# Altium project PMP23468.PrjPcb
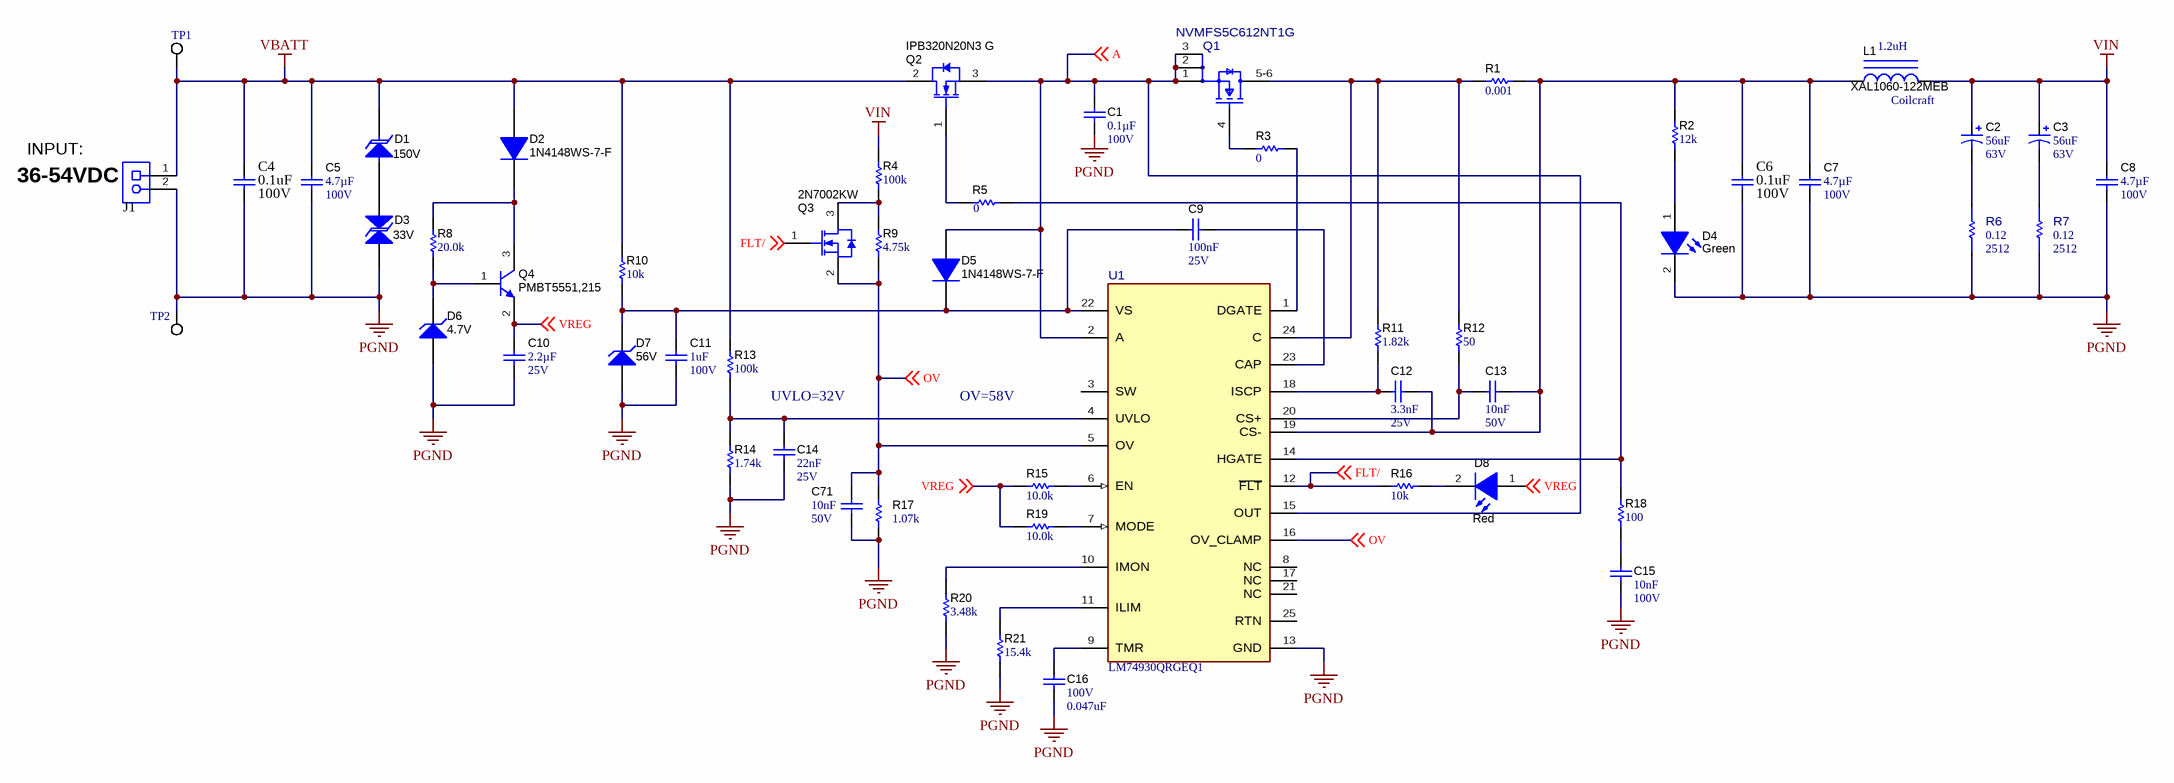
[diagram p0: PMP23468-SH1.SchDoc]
CopyrightYear: 2018; PCB_Layout: Who did the Layout?; PCB_Rev: E1; PRJ_Customer: Public Release; PRJ_Engineer: Enter name of project lead; PRJ_Number: XXX###; PRJ_Title: Change in menu Project|Project Options|Parameters; SCH_Rev: E1; TechSupport: http://www.ti.com/support; TID: N/A
2 sheets, 157 parts. Net scope: global (net labels, ports and power ports of the same name join across sheets).
Board file: PMP23468A.PcbDoc
Sheets:
  PMP23468-SH1.SchDoc
  PMP23468-SH2.SchDoc

## Sheet PMP23468-SH1.SchDoc: LM25143-Q1 Two Phases
size 431 x 279 mm; Date: Not shown in title block; ApprovedBy: Not shown in title block; CheckedBy: Not shown in title block; Author: Not shown in title block; CompanyName: Not shown in title block; Engineer: Not shown in title block; Organization: Not shown in title block; Address1: Not shown in title block; Address2: Not shown in title block; Address3: Not shown in title block; Address4: Not shown in title block; DocumentNumber: 1; Revision: Use project parameter SCH_Rev; SheetNumber: 1; SheetTotal: 2; PageSetup: Record=PageOptions¦CenterHorizontal=True¦CenterVertical=True¦PrintScale=0.96¦XCorrection=1.00¦YCorrection=1.00¦PrintKind=0¦BorderSize=5000000¦LeftOffset=0¦BottomOffset=0¦Orientation=2¦PaperLength=1000¦PaperWidth=1000¦Scale=100¦PaperSource=7¦PrintQuality=600¦MediaType=1¦DitherType=10¦PaperKind=11" x 17"¦PrintScaleMode=1

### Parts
C1  ValueDisplayed: 0.1µF  VDC_V: 100V  [0603]  (hidden comment: GCJ188L8EL104KA07D)
C2  VDC_V: 63V  ValueDisplayed: 56uF  [SM_RADIAL_10BMM]  (hidden comment: EEHZC1J560P)
C3  VDC_V: 63V  ValueDisplayed: 56uF  [SM_RADIAL_10BMM]  (hidden comment: EEHZC1J560P)
C4  Value2: 100V  ValueDisplayed: 0.1uF  [0805_HV]  (hidden comment: C0805C104K1RACTU)
C5  VDC_V: 100V  ValueDisplayed: 4.7µF  [1210_220]  (hidden comment: GCM32DC72A475KE02L)
C6  Value2: 100V  ValueDisplayed: 0.1uF  [0805_HV]  (hidden comment: C0805C104K1RACTU)
C7  VDC_V: 100V  ValueDisplayed: 4.7µF  [1210_220]  (hidden comment: GCM32DC72A475KE02L)
C8  VDC_V: 100V  ValueDisplayed: 4.7µF  [1210_220]  (hidden comment: GCM32DC72A475KE02L)
C9  Cap_F: 100nF  VDC_V: 25V  [0603]  (hidden comment: CGA3E2X7R1E104K080AA)
C10  Cap_F: 2.2µF  VDC_V: 25V  [0805_HV]  (hidden comment: GCM21BR71E225KA73L)
C11  VDC_V: 100V  ValueDisplayed: 1uF  [1206_180]  (hidden comment: GCM31CR72A105KA03)
C12  Cap_F: 3.3nF  VDC_V: 25V  [0603]  (hidden comment: GRM188R71E332KA01D)
C13  Cap_F: 10nF  VDC_V: 50V  [0603]  (hidden comment: GCM188R71H103KA37D)
C14  Cap_F: 22nF  VDC_V: 25V  [0603]  (hidden comment: C0603C223K3RACTU)
C15  Cap_F: 10nF  VDC_V: 100V  [0603]  (hidden comment: CGA3E2X7R2A103K080AA)
C16  VDC_V: 100V  ValueDisplayed: 0.047uF  [0603]  (hidden comment: CGA3E3X7S2A473K080AB)
C71  Cap_F: 10nF  VDC_V: 50V  [0603]  (hidden comment: GCM188R71H103KA37D)
D1  value 150V  [SMB]  (hidden comment: SMBJ150A-13-F)
D2  1N4148WS-7-F  [SOD-323]
D3  value 33V  [SMB-Bi]  (hidden comment: SMBJ33CA-13-F)
D4  value Green  [LED_LTST-C190]  (hidden comment: LTST-C190GKT)
D5  1N4148WS-7-F  [SOD-323]
D6  value 4.7V  [SOD-323]  (hidden comment: MM3Z4V7ST1G)
D7  value 56V  [SOD-123]  (hidden comment: MMSZ5263BT1G)
D8  value Red  [LED_LTST-C170_Red]  (hidden comment: LTST-C170KRKT)
J1  1714971  [Phoenix_1714971]  (value not drawn)
L1  XAL1060-122MEB  Manufacturer: Coilcraft  ValueDisplayed: 1.2uH  [XAL1060]
Q1  NVMFS5C612NT1G  [FP-NVMFS5C612NT1G_DFN5-MFG]
Q2  IPB320N20N3 G  [DDPAK]
Q3  2N7002KW  [SOT-323]
Q4  PMBT5551,215  [SOT-23]
R1  ValueDisplayed: 0.001  [2010]  (hidden comment: WSL20101L000FEA)
R2  ValueDisplayed: 12k  [0603]  (hidden comment: CRCW060312K0JNEA)
R3  ValueDisplayed: 0  [0603]  (hidden comment: ERJ-3GEY0R00V)
R4  ValueDisplayed: 100k  [0603]  (hidden comment: CRCW0603100KFKEA)
R5  ValueDisplayed: 0  [0603]  (hidden comment: ERJ-3GEY0R00V)
R6  PackageReference: 2512  Res_ohm: 0.12  [FP-TLRH3AWTTER120F_2512-MFG]  (hidden comment: TLRH3AWTTER120F)
R7  PackageReference: 2512  Res_ohm: 0.12  [FP-TLRH3AWTTER120F_2512-MFG]  (hidden comment: TLRH3AWTTER120F)
R8  ValueDisplayed: 20.0k  [0805_HV]  (hidden comment: ERJ-6ENF2002V)
R9  ValueDisplayed: 4.75k  [0603]  (hidden comment: CRCW06034K75FKEA)
R10  ValueDisplayed: 10k  [1206]  (hidden comment: CRCW120610K0JNEA)
R11  ValueDisplayed: 1.82k  [0603]  (hidden comment: CRCW0603464RFKEA)
R12  ValueDisplayed: 50  [0603]  (hidden comment: CRCW060350R0FKEA)
R13  ValueDisplayed: 100k  [0603]  (hidden comment: CRCW0603100KFKEA)
R14  ValueDisplayed: 1.74k  [0603]  (hidden comment: CRCW06031K74FKEA)
R15  ValueDisplayed: 10.0k  [0603]  (hidden comment: RMCF0603FT10K0)
R16  ValueDisplayed: 10k  [1206]  (hidden comment: CRCW120610K0JNEA)
R17  ValueDisplayed: 1.07k  [0603]  (hidden comment: CRCW06031K10FKEA)
R18  ValueDisplayed: 100  [0603]  (hidden comment: CRCW0603100RJNEA)
R19  ValueDisplayed: 10.0k  [0603]  (hidden comment: RMCF0603FT10K0)
R20  ValueDisplayed: 3.48k  [0603]  (hidden comment: RC0603FR-0736KL)
R21  ValueDisplayed: 15.4k  [0603]  (hidden comment: CRCW060324K3FKEA)
TP1  5015  [Testpoint_Keystone_Miniature]  (value not drawn)
TP2  5015  [Testpoint_Keystone_Miniature]  (value not drawn)
U1  LM74930QRGEQ1  [RGE0024T-MFG]

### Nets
PGND: C1.2 C4.1 C5.2 C6.2 C7.2 C8.2 C10.2 C11.2 C14.2 C15.2 C16.2 C71.1 D3.2 D4.2(K) D6.2(A) D7.2(A) J1.2 R6.1 R7.1 R14.2 R17.2 R20.1 R21.2 TP2.1 U1.13(GND)
VBATT: C4.2 C5.1 D1.1(K) D2.2(A) J1.1 Q2.2(D) R10.1 R13.1 TP1.1
VIN: C2.1(+) C3.1(+) C8.1 L1.2 R4.1
A: C1.1 D5.2(A) Q1.1(S) Q1.2(S) Q1.3(S) Q2.3(S) U1.2(A) U1.15(OUT) ; off-sheet A
FLT/: Q3.1(G) R16.1 U1.12(~{FLT}) ; off-sheet FLT/
OV: C71.2 Q3.2(S) R9.2 R17.1 U1.5(OV) U1.16(OV_CLAMP) ; off-sheet OV
VREG: C10.1 D8.1(A) Q4.2(E) R15.1 R19.1 ; off-sheet VREG
NetC2_2: C2.2(-) R6.2
NetC3_2: C3.2(-) R7.2
NetC6_1: C6.1 C7.1 C12.2 C13.2 L1.1 R1.2 R2.1 U1.19(CS-)
NetC9_1: C9.1 C11.1 D5.1(K) D7.1(K) R10.2 U1.22(VS)
NetC9_2: C9.2 U1.23(CAP)
NetC12_1: C12.1 R11.2 U1.18(ISCP)
NetC13_1: C13.1 R12.2 U1.20(CS+)
NetC14_1: C14.1 R13.2 R14.1 U1.4(UVLO)
NetC15_1: C15.1 R18.2
NetC16_1: C16.1 U1.9(TMR)
NetD1_2: D1.2(A) D3.1
NetD2_1: D2.1(K) Q4.3(C) R8.1
NetD4_1: D4.1(A) R2.2
NetD6_1: D6.1(K) Q4.1(B) R8.2
NetD8_2: D8.2(K) R16.2
NetQ1_4: Q1.4(G) R3.1
NetQ1_5-6: Q1.5-6(D) R1.1 R11.1 R12.1 U1.24(C)
NetQ2_1: Q2.1(G) R5.1
NetQ3_3: Q3.3(D) R4.2 R9.1
NetR3_2: R3.2 U1.1(DGATE)
NetR5_2: R5.2 R18.1 U1.14(HGATE)
NetR15_2: R15.2 U1.6(EN)
NetR19_2: R19.2 U1.7(MODE)
NetR20_2: R20.2 U1.10(IMON)
NetR21_1: R21.1 U1.11(ILIM)

Not connected (* = marked no-connect by the designer): U1 3(SW) 8(NC) 17(NC) 21(NC) 25(RTN)

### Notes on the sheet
- INPUT:
- (near J1) 36-54VDC
- UVLO=32V
- OV=58V

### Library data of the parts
C1 = CMP-0860999-1: CAP, CERM, 0.1 µF, 100 V,+/- 10%, X8L, AEC-Q200 Grade 0, 0603; Manufacturer: MuRata; Cap_F: 100nF; TaMax_C: 150°C; SizeAreaWB_mm2: 4.68; SizeArea_mm2: 1.28; Value: 0.1uF; SizeZ_mm: 1; AEC Qualified: Y; SizeX_mm: 1.6; AEC Grade: 0; SizeY_mm: 0.8; U/M: EA; TaMin_C: -55°C; Polarized: N; AEC Category: Q200
C2 C3 = CMP-0012603-3: CAP, Polymer Hybrid, 56 uF, 63 V, +/- 20%, 30 ohm, 10x10 SMD; Manufacturer: Panasonic; TaMin_C: -55°C; ESR_ohm: 30; Polarized: Y; SizeAreaWB_mm2: 159.9; Value1: 30 ohm; Value: 56uF; TaMax_C: 125°C; SizeZ_mm: 10.2; SizeX_mm: 11; SizeY_mm: 10.3; SizeArea_mm2: 113.3; CompType: Capacitor; Cap_F: 56µF; IRMS_A: 1.4A; AEC Category: Q200
C4 C6 = CMP-0007722-2: CAP, CERM, 0.1 uF, 100 V, +/- 10%, X7R, 0805; Manufacturer: Kemet; TaMin_C: -55°C; ESR_ohm: 0.064; Polarized: N; SizeAreaWB_mm2: 6.75; Value1: 0.064 ohm; U/M: EA; Value: 0.1uF; TaMax_C: 125°C; SizeZ_mm: 1.45; SizeX_mm: 2; SizeY_mm: 1.25; Cap_Case: 0805; SizeArea_mm2: 2.5; CompType: Capacitor; Cap_F: 100nF; IRMS_A: 1.64A; AEC Category: Q200
C5 C7 C8 = CMP-0082268-1: CAP, CERM, 4.7 µF, 100 V,+/- 10%, X7S, AEC-Q200 Grade 1, 1210; Manufacturer: MuRata; TaMin_C: -55°C; ESR_ohm: 1m; Polarized: N; SizeAreaWB_mm2: 14.7; Value1: 0.001 ohm; U/M: EA; Value: 4.7uF; TaMax_C: 125°C; SizeZ_mm: 2.2; SizeX_mm: 3.2; SizeY_mm: 2.5; Cap_Case: 1210; SizeArea_mm2: 8; AEC Qualified: Y; IRMS_A: 6A; AEC Grade: 1; AEC Category: Q200
C9 = CMP-0007077-5: CAP, CERM, 0.1 uF, 25 V, +/- 10%, X7R, AEC-Q200 Grade 1, 0603; Manufacturer: TDK; TaMin_C: -55°C; Polarized: N; SizeAreaWB_mm2: 4.68; Value1: Unknown; U/M: EA; Value: 0.1uF; TaMax_C: 125°C; SizeZ_mm: 1; SizeX_mm: 1.6; SizeY_mm: 0.8; SizeArea_mm2: 1.28; AEC Qualified: Y; AEC Category: Q200
C10 = CMP-0083622-1: CAP, CERM, 2.2 µF, 25 V,+/- 10%, X7R, AEC-Q200 Grade 1, 0805; Manufacturer: MuRata; TaMin_C: -55°C; Polarized: N; SizeAreaWB_mm2: 6.75; U/M: EA; Value: 2.2uF; TaMax_C: 125°C; SizeZ_mm: 1.45; SizeX_mm: 2; SizeY_mm: 1.25; Cap_Case: 0805; SizeArea_mm2: 2.5; AEC Qualified: Y; AEC Grade: 1; AEC Category: Q200
C11 = CMP-0008815-2: CAP, CERM, 1 uF, 100 V, +/- 10%, X7R, AEC-Q200 Grade 1, 1206; Manufacturer: MuRata; TaMin_C: -55°C; Polarized: N; SizeAreaWB_mm2: 10.92; Value1: Unknown; U/M: EA; Value: 1uF; TaMax_C: 125°C; SizeZ_mm: 1.8; SizeX_mm: 3.2; SizeY_mm: 1.6; Cap_Case: 1206; SizeArea_mm2: 5.12; AEC Qualified: Y; Cap_F: 1µF; AEC Grade: 1; AEC Category: Q200
C12 = CMP-0007418-4: CAP, CERM, 3300 pF, 25 V, +/- 10%, X7R, 0603; Manufacturer: MuRata; TaMin_C: -55°C; Polarized: N; SizeAreaWB_mm2: 4.68; Value1: Unknown; U/M: EA; Value: 3300pF; TaMax_C: 125°C; SizeZ_mm: 1; SizeX_mm: 1.6; SizeY_mm: 0.8; SizeArea_mm2: 1.28; AEC Category: Q200
C13 = CMP-0007143-4: CAP, CERM, 0.01 uF, 50 V, +/- 10%, X7R, AEC-Q200 Grade 1, 0603; Manufacturer: MuRata; TaMin_C: -55°C; Polarized: N; SizeAreaWB_mm2: 4.68; Value1: Unknown; U/M: EA; Value: 0.01uF; TaMax_C: 125°C; SizeZ_mm: 1; SizeX_mm: 1.6; SizeY_mm: 0.8; SizeArea_mm2: 1.28; AEC Qualified: Y; AEC Category: Q200
C14 = CMP-0006899-4: CAP, CERM, 0.022 uF, 25 V, +/- 10%, X7R, 0603; Manufacturer: Kemet; TaMin_C: -55°C; Polarized: N; SizeAreaWB_mm2: 4.68; Value1: Unknown; U/M: EA; TaMax_C: 125°C; SizeZ_mm: 1; SizeX_mm: 1.6; SizeY_mm: 0.8; SizeArea_mm2: 1.28; AEC Category: Q200
C15 = CMP-0007082-4: CAP, CERM, 0.01 uF, 100 V, +/- 10%, X7R, AEC-Q200 Grade 1, 0603; Manufacturer: TDK; TaMin_C: -55°C; ESR_ohm: 0.2354; Polarized: N; SizeAreaWB_mm2: 4.68; Value1: 0.235428 ohm; U/M: EA; Value: 0.01uF; TaMax_C: 125°C; SizeZ_mm: 1; SizeX_mm: 1.6; SizeY_mm: 0.8; SizeArea_mm2: 1.28; AEC Qualified: Y; IRMS_A: 396.995mA; AEC Category: Q200
C16 = CMP-0007101-4: CAP, CERM, 0.047 uF, 100 V, +/- 10%, X7S, AEC-Q200 Grade 1, 0603; Manufacturer: TDK; TaMin_C: -55°C; ESR_ohm: 89.796m; Polarized: N; SizeAreaWB_mm2: 4.68; Value1: 0.089796 ohm; U/M: EA; TaMax_C: 125°C; SizeZ_mm: 1; SizeX_mm: 1.6; SizeY_mm: 0.8; SizeArea_mm2: 1.28; AEC Qualified: Y; Cap_F: 47nF; IRMS_A: 567.484mA; AEC Category: Q200
C71 = CMP-0007143-4: CAP, CERM, 0.01 uF, 50 V, +/- 10%, X7R, AEC-Q200 Grade 1, 0603 (stack on top of R17 resistor); Manufacturer: MuRata; TaMin_C: -55°C; Polarized: N; SizeAreaWB_mm2: 4.68; Value1: Unknown; U/M: EA; Value: 0.01uF; TaMax_C: 125°C; SizeZ_mm: 1; SizeX_mm: 1.6; SizeY_mm: 0.8; SizeArea_mm2: 1.28; AEC Qualified: Y; AEC Category: Q200
D1 = CMP-0005577-3: Diode, TVS, Uni, 150 V, 243 Vc, SMB; Manufacturer: Diodes Inc.; Vbr_Max: 192.5V; Ipp: 2.5A; AEC Category: Q101; SizeArea_mm2: 21.336; Value1: 600W; SizeAreaWB_mm2: 44.156; Vc: 243V; SizeZ_mm: 2.6; SizeX_mm: 5.6; SizeY_mm: 3.81; Vbr_Min: 167V
D2 D5 = CMP-0079597-2: Diode, Switching, 75 V, 0.15 A, AEC-Q101, SOD-323; Manufacturer: Diodes Inc.; SizeX_mm: 2.7; Vf_V: 1.25V; AEC Qualified: Y; SizeArea_mm2: 3.645; AEC Category: Q101; SizeAreaWB_mm2: 8.695; Io_A: 150mA; SizeZ_mm: 1; Value1: 0.15A; SizeY_mm: 1.35; TJmax_C: 150°C; Vr_V: 75V; Value: 75V
D3 = CMP-0005564-3: Diode, TVS, Bi, 33 V, SMB; Manufacturer: Diodes Inc.; SizeX_mm: 5.6; Ppk: 600W; SizeAreaWB_mm2: 44.156; SizeZ_mm: 2.6; SizeArea_mm2: 21.336; SizeY_mm: 3.81; AEC Category: Q101
D4 = CMP-0002827-3: LED, Green, SMD; Manufacturer: Lite-On; Power_TotalModule: 100mW; Value2: 2.1V; Io_A: 20mA; Value1: 0.1W
D6 = CMP-0085737-1: Diode, Zener, 4.7 V, 300 mW, SOD-323; Manufacturer: ON Semiconductor; SizeArea_mm2: 3.645; SizeZ_mm: 1; SizeAreaWB_mm2: 8.695; RJA_CperW: 416; SizeY_mm: 1.35; Power_W: 300mW; AEC Qualified: N; SizeX_mm: 2.7; AEC Category: Q101; Value1: 0.3W
D7 = CMP-0005738-4: Diode, Zener, 56 V, 500 mW, AEC-Q101, SOD-123; Manufacturer: ON Semiconductor; AEC Qualified: Y; Value1: 0.5W; SizeY_mm: 1.7; SizeX_mm: 3.85; SizeArea_mm2: 6.545; AEC Category: Q101; SizeAreaWB_mm2: 13.095; Power_W: 500mW; SizeZ_mm: 1.35; RJA_CperW: 340
D8 = CMP-0002829-3: LED, Red, SMD; Manufacturer: Lite-On; SizeZ_mm: 1.2; Value1: W; SizeY_mm: 1.25; Value2: 2V; SizeArea_mm2: 2.5; SizeX_mm: 2; SizeAreaWB_mm2: 6.75; Io_A: 20mA; Type: AlInGaP
J1 = CMP-0055554-1: Receptacle, 9.52mm, 2x1, TH; Manufacturer: Phoenix Contact; CNHeader: FALSE; Current_A: 32A; Gender: Female; Cert_CSA: Y; Voltage_V: 1kV; Row_Count: 1; Pitch_mm: 9.52
L1 = CMP-0060959-1: Inductor, Shielded, Composite, 1.2 uH, 26.3 A, 0.0025 ohm, AEC-Q200 Grade 1, SMD; Isat: 43A @ 30% inductance drop; Irms: 26.3A @ 40C rise; Green_Lifecycle: Not Set; SizeAreaWB_mm2: 159.6; DCR_ohm: 2.5m; Green_REACh: Incomplete; Value: 1.2uH; Imax_A: 26.3A; SizeZ_mm: 6; SizeX_mm: 11.3; SizeY_mm: 10; SizeArea_mm2: 113; Ind_H: 1.2µH; AEC Qualified: Y; AEC Grade: 1; AEC Category: Q200
Q1 = CMP-0093804-1: Single N-Channel Power MOSFET 60V, 225A, 1.65ohm; Manufacturer: onsemi; Turn On Delay Time: 13.2ns; Standoff Height: 0mm; TJmax_C: +175°C; Rdson45_ohm: 1.35m; Turn Off Delay Time: 46.5ns; Number Of N Channels: 1; Vgs_V: 20V; Reverse Recovery Charge: 160nC; AEC Grade: Grade 0; Threshold Vgs Min: 2V; Rthja Max: 39°C/W; QgTyp_nC: 62nC @ 10V; Reverse Recovery Time: 90ns; VdsMax_V: 1.2V; Input Capacitace At Vds: 4900pF @ 25V; Power_W: 3.8W; AEC Qualified: Yes; SizeZ_mm: 1.1mm; Pulse Drain Current: 900A; ChMode: False; Threshold Vgs Max: 4V; Typ Forward Diode Voltage: 0.81V
Q2 = CMP-0001084-3: MOSFET, N-CH, 200 V, 34 A, DDPAK; Manufacturer: Infineon Technologies; Alternate Manufacturer: None; Value2: 22 nC; QgTyp_nC: 22; SizeZ_mm: 4.445; Value: 200V; SizeAreaWB_mm2: 209.6992; Rdson45_ohm: 0.25; Value1: 0.2; SizeArea_mm2: 154.8892; AEC Category: Q101; ChMode: Enhancement; SizeY_mm: 10.16; SizeX_mm: 15.245; ChType: N; Vgs_V: 20V; IdsMax_A: 34A
Q3 = CMP-0000774-1: MOSFET, N-CH, 60 V, 0.31 A, SOT-323; Manufacturer: Fairchild Semiconductor; Alternate Manufacturer: None; SizeZ_mm: 1.1; Value: 60V; SizeAreaWB_mm2: 10.24; Rdson45_ohm: 1.6; Value1: 1; SizeArea_mm2: 4.84; AEC Category: Q101; SizeY_mm: 2.2; ChType: N; Vgs_V: 2.1V; IdsMax_A: 310mA; U/M: EA
Q4 = CMP-0750056-1: Transistor, NPN, 160 V, 0.3 A, SOT-23; Manufacturer: Nexperia; TaMax_C: 150°C; IcRated_A: 300mA; SizeX_mm: 2.5; NPN: 1; AEC Qualified: N; TaMin_C: -65°C; PNP: 0; SizeArea_mm2: 7.5; SizeY_mm: 3; SizeAreaWB_mm2: 14; CompType: BJT; SizeZ_mm: 1.1; Vcesat1_V: 150mV; Value: 160 V; Value2: 250; Vceo_V: 160V; AEC Category: Q101; Value1: 0.3 A
R1 = CMP-0016548-2: RES, 0.001, 1%, 0.5 W, 2010; Manufacturer: Vishay-Dale; Power_W: 500mW; TempCo: 275 ppm/C; Value_Code: 1L000; U/M: EA; Value: 0.001; EIA_Code: E96; Res_ohm: 1m; SizeX_mm: 5; SizeY_mm: 2.5; SizeZ_mm: 1.66; Value2: 0.5W; SizeArea_mm2: 12.5; AEC Category: Q200
R2 = CMP-0025711-4: RES, 12 k, 5%, 0.1 W, AEC-Q200 Grade 0, 0603; Manufacturer: Vishay-Dale; Power_W: 100mW; TempCo: 200 ppm/C; Value_Code: 12k0; Value: 12k; EIA_Code: E24; SizeX_mm: 1.6; SizeY_mm: 0.8; SizeZ_mm: 1; Value2: 0.1W; SizeArea_mm2: 1.28; AEC Qualified: Y; VDC_V: 75V; AEC Category: Q200; AEC Grade: 0
R3 R5 = CMP-0025874-4: RES, 0, 5%, 0.1 W, AEC-Q200 Grade 0, 0603; Manufacturer: Panasonic; Power_W: 100mW; TempCo: 600 ppm/C; Value_Code: 0000; Value: 0; EIA_Code: E24; SizeX_mm: 1.6; SizeY_mm: 0.8; SizeZ_mm: 1; Value2: 0.1W; SizeArea_mm2: 1.28; AEC Qualified: Y; VDC_V: 50V; AEC Category: Q200; SizeAreaWB_mm2: 4.68
R4 R13 = CMP-0021990-4: RES, 100 k, 1%, 0.1 W, AEC-Q200 Grade 0, 0603; Manufacturer: Vishay-Dale; Power_W: 100mW; TempCo: 100 ppm/C; Value: 100k; EIA_Code: E96; SizeX_mm: 1.6; SizeY_mm: 0.8; SizeZ_mm: 1; Value2: 0.1W; SizeArea_mm2: 1.28; AEC Qualified: Y; VDC_V: 75V; AEC Category: Q200; AEC Grade: 0
R6 R7 = CMP-0088454-1: 120 mOhms ±1% 2W Chip Resistor 2512 (6432 Metric) Automotive AEC-Q200, Current Sense Metal Element; Manufacturer: KOA Speer; TempCo: 50ppm/°C; SizeZ_mm: 0.7mm; AEC Qualified: Yes; AEC Grade: Grade 0
R8 = CMP-0021614-3: RES, 20.0 k, 1%, 0.125 W, AEC-Q200 Grade 0, 0805; Manufacturer: Panasonic; Power_W: 125mW; TempCo: 100 ppm/C; Value_Code: 20k0; Value: 20.0k; EIA_Code: E96; Res_ohm: 20k; SizeX_mm: 2; SizeY_mm: 1.25; SizeZ_mm: 1.45; Value2: 0.125W; SizeArea_mm2: 2.5; AEC Qualified: Y; AEC Category: Q200; AEC Grade: 0; SizeAreaWB_mm2: 6.75
R9 = CMP-0022456-4: RES, 4.75 k, 1%, 0.1 W, AEC-Q200 Grade 0, 0603; Manufacturer: Vishay-Dale; Power_W: 100mW; TempCo: 100 ppm/C; Value_Code: 4k75; Value: 4.75k; EIA_Code: E96; SizeX_mm: 1.6; SizeY_mm: 0.8; SizeZ_mm: 1; Value2: 0.1W; SizeArea_mm2: 1.28; AEC Qualified: Y; VDC_V: 75V; AEC Category: Q200; AEC Grade: 0
R10 R16 = CMP-0018576-3: RES, 10 k, 5%, 0.25 W, AEC-Q200 Grade 0, 1206; Manufacturer: Vishay-Dale; Power_W: 250mW; TempCo: 200 ppm/C; Value_Code: 10k0; Value: 10k; EIA_Code: E24; SizeX_mm: 3.2; SizeY_mm: 1.6; SizeZ_mm: 1.35; Value2: 0.25W; SizeArea_mm2: 5.12; AEC Qualified: Y; VDC_V: 200V; AEC Category: Q200; AEC Grade: 0
R11 = CMP-0022134-4: RES, 1.82 k, 1%, 0.1 W, AEC-Q200 Grade 0, 0603; Manufacturer: Vishay-Dale; PartNumber: CRCW06031K82FKEA; Power_W: 100mW; TempCo: 100 ppm/C; Value_Code: 1k82; Value: 1.82k; EIA_Code: E96; SizeX_mm: 1.6; SizeY_mm: 0.8; SizeZ_mm: 1; Value2: 0.1W; SizeArea_mm2: 1.28; AEC Qualified: Y; VDC_V: 75V; AEC Category: Q200; AEC Grade: 0
R12 = CMP-0022479-4: RES, 50, 1%, 0.1 W, AEC-Q200 Grade 0, 0603; Manufacturer: Vishay-Dale; Power_W: 100mW; TempCo: 100 ppm/C; Value_Code: 50R0; Value: 50; SizeX_mm: 1.6; SizeY_mm: 0.8; SizeZ_mm: 1; Value2: 0.1W; SizeArea_mm2: 1.28; AEC Qualified: Y; VDC_V: 75V; AEC Category: Q200; AEC Grade: 0
R14 = CMP-0022132-4: RES, 1.74 k, 1%, 0.1 W, AEC-Q200 Grade 0, 0603; Manufacturer: Vishay-Dale; Power_W: 100mW; TempCo: 100 ppm/C; Value_Code: 1k74; Value: 1.74k; EIA_Code: E96; SizeX_mm: 1.6; SizeY_mm: 0.8; SizeZ_mm: 1; Value2: 0.1W; SizeArea_mm2: 1.28; AEC Qualified: Y; VDC_V: 75V; AEC Category: Q200; AEC Grade: 0
R15 R19 = CMP-0023341-3: RES, 10.0 k, 1%, 0.1 W, AEC-Q200 Grade 0, 0603; Manufacturer: Stackpole Electronics Inc; Power_W: 100mW; TempCo: 100 ppm/C; Value_Code: 10k0; U/M: EA; Value: 10.0k; EIA_Code: E96; Res_ohm: 10k; SizeX_mm: 1.6; SizeY_mm: 0.8; SizeZ_mm: 1; Value2: 0.1W; SizeArea_mm2: 1.28; AEC Qualified: Y; VDC_V: 75V; AEC Grade: 0; AEC Category: Q200
R17 = CMP-0022112-4: RES, 1.07 k, 1%, 0.1 W, AEC-Q200 Grade 0, 0603; Manufacturer: Vishay-Dale; PartNumber: CRCW06031K07FKEA; Power_W: 100mW; TempCo: 100 ppm/C; Value_Code: 1k07; Value: 1.07k; EIA_Code: E96; SizeX_mm: 1.6; SizeY_mm: 0.8; SizeZ_mm: 1; Value2: 0.1W; SizeArea_mm2: 1.28; AEC Qualified: Y; VDC_V: 75V; AEC Category: Q200; AEC Grade: 0
R18 = CMP-0025700-4: RES, 100, 5%, 0.1 W, AEC-Q200 Grade 0, 0603; Manufacturer: Vishay-Dale; Power_W: 100mW; TempCo: 200 ppm/C; Value_Code: 100R; Value: 100; EIA_Code: E24; SizeX_mm: 1.6; SizeY_mm: 0.8; SizeZ_mm: 1; Value2: 0.1W; SizeArea_mm2: 1.28; AEC Qualified: Y; VDC_V: 75V; AEC Category: Q200; AEC Grade: 0
R20 = CMP-0022377-4: RES, 3.48 k, 1%, 0.1 W, AEC-Q200 Grade 0, 0603; Manufacturer: Vishay-Dale; PartNumber: CRCW06033K48FKEA; Power_W: 100mW; TempCo: 100 ppm/C; Value_Code: 3k48; Value: 3.48k; EIA_Code: E96; SizeX_mm: 1.6; SizeY_mm: 0.8; SizeZ_mm: 1; Value2: 0.1W; SizeArea_mm2: 1.28; AEC Qualified: Y; VDC_V: 75V; AEC Category: Q200; AEC Grade: 0
R21 = CMP-0022067-4: RES, 15.4 k, 1%, 0.1 W, AEC-Q200 Grade 0, 0603; Manufacturer: Vishay-Dale; PartNumber: CRCW060315K4FKEA; Power_W: 100mW; TempCo: 100 ppm/C; Value_Code: 15k4; Value: 15.4k; EIA_Code: E96; SizeX_mm: 1.6; SizeY_mm: 0.8; SizeZ_mm: 1; Value2: 0.1W; SizeArea_mm2: 1.28; AEC Qualified: Y; VDC_V: 75V; AEC Category: Q200; AEC Grade: 0
TP1 TP2 = CMP-0055152-2: Test Point, Miniature, SMT; Manufacturer: Keystone Electronics; CNHeader: FALSE; Green_Lifecycle: Active; Green_REACh: Passed; CT: TRUE
U1 = CMP-0021701-1: Ideal Diode Surge Stopper with Circuit breaker, overvoltage protection and fault output; Manufacturer: Texas Instruments; SizeZ_mm: 1mm; AEC Qualified: Yes; AEC Grade: Grade 1; Max Supply Voltage: 65V; Min Supply Voltage: 3V; Nominal Supply Current: 650-700uA; Number Of Outputs: 1; Standoff Height: 0mm; TaMax_C: +125°C; TaMin_C: -40°C; TJmax_C: +150°C

## Sheet PMP23468-SH2.SchDoc: LM25143-Q1 Two Phases
size 431 x 279 mm; Date: Not shown in title block; ApprovedBy: Not shown in title block; CheckedBy: Not shown in title block; Author: Not shown in title block; CompanyName: Not shown in title block; Engineer: Not shown in title block; Organization: Not shown in title block; Address1: Not shown in title block; Address2: Not shown in title block; Address3: Not shown in title block; Address4: Not shown in title block; DocumentNumber: 2; Revision: Use project parameter SCH_Rev; SheetNumber: 2; SheetTotal: 2; PageSetup: Record=PageOptions¦CenterHorizontal=True¦CenterVertical=True¦PrintScale=0.96¦XCorrection=1.00¦YCorrection=1.00¦PrintKind=0¦BorderSize=5000000¦LeftOffset=0¦BottomOffset=0¦Orientation=2¦PaperLength=1000¦PaperWidth=1000¦Scale=100¦PaperSource=7¦PrintQuality=600¦MediaType=1¦DitherType=10¦PaperKind=11" x 17"¦PrintScaleMode=1
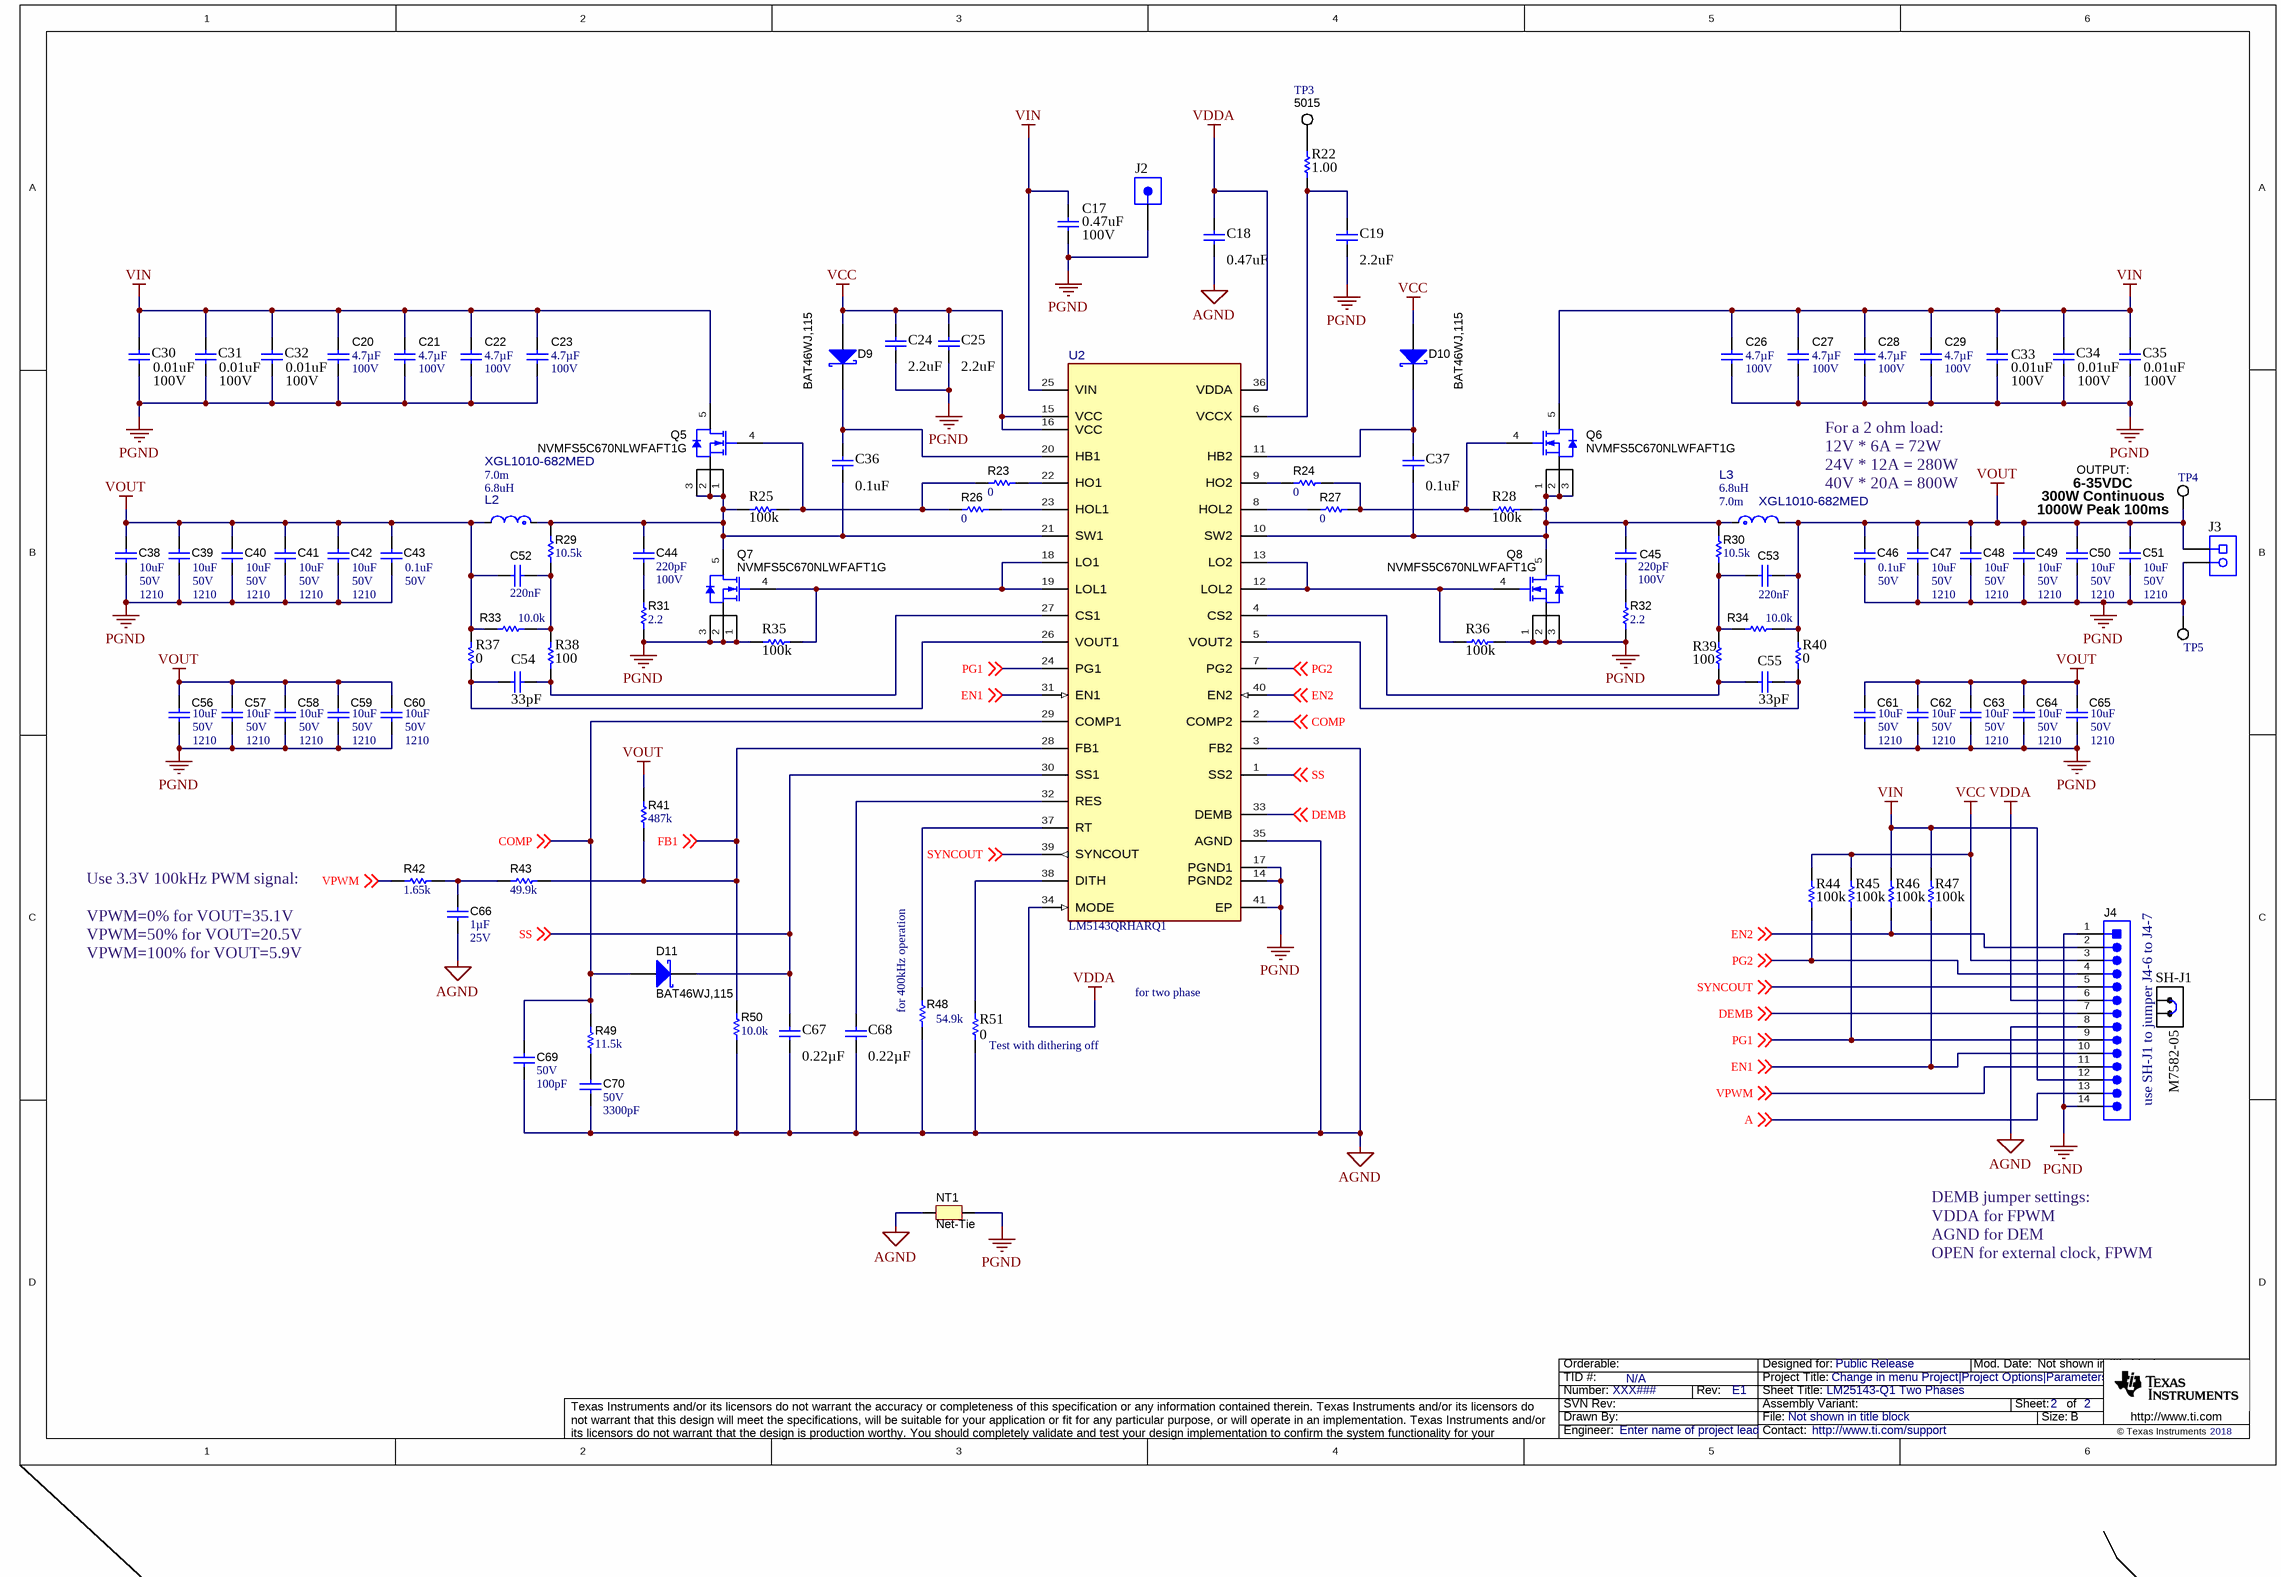
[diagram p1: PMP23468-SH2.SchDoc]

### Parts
C17  VDC_V: 100V  ValueDisplayed: 0.47uF  [0805L]  (hidden comment: GRM21BR72A474KA73L)
C18  ValueDisplayed: 0.47uF  [0603L]  (hidden comment: GCM188R71C474KA55D)
C19  ValueDisplayed: 2.2uF  [0603L]  (hidden comment: GRM188R71A225KE15D)
C20  VDC_V: 100V  ValueDisplayed: 4.7µF  [1210_220]  (hidden comment: GCM32DC72A475KE02L)
C21  VDC_V: 100V  ValueDisplayed: 4.7µF  [1210_220]  (hidden comment: GCM32DC72A475KE02L)
C22  VDC_V: 100V  ValueDisplayed: 4.7µF  [1210_220]  (hidden comment: GCM32DC72A475KE02L)
C23  VDC_V: 100V  ValueDisplayed: 4.7µF  [1210_220]  (hidden comment: GCM32DC72A475KE02L)
C24  ValueDisplayed: 2.2uF  [0603L]  (hidden comment: GRM188R71A225KE15D)
C25  ValueDisplayed: 2.2uF  [0603L]  (hidden comment: GRM188R71A225KE15D)
C26  VDC_V: 100V  ValueDisplayed: 4.7µF  [1210_220]  (hidden comment: GCM32DC72A475KE02L)
C27  VDC_V: 100V  ValueDisplayed: 4.7µF  [1210_220]  (hidden comment: GCM32DC72A475KE02L)
C28  VDC_V: 100V  ValueDisplayed: 4.7µF  [1210_220]  (hidden comment: GCM32DC72A475KE02L)
C29  VDC_V: 100V  ValueDisplayed: 4.7µF  [1210_220]  (hidden comment: GCM32DC72A475KE02L)
C30  VDC_V: 100V  ValueDisplayed: 0.01uF  [0402S]  (hidden comment: CGA2B3X7S2A103K050BB)
C31  VDC_V: 100V  ValueDisplayed: 0.01uF  [0402S]  (hidden comment: CGA2B3X7S2A103K050BB)
C32  VDC_V: 100V  ValueDisplayed: 0.01uF  [0402S]  (hidden comment: CGA2B3X7S2A103K050BB)
C33  VDC_V: 100V  ValueDisplayed: 0.01uF  [0402S]  (hidden comment: CGA2B3X7S2A103K050BB)
C34  VDC_V: 100V  ValueDisplayed: 0.01uF  [0402S]  (hidden comment: CGA2B3X7S2A103K050BB)
C35  VDC_V: 100V  ValueDisplayed: 0.01uF  [0402S]  (hidden comment: CGA2B3X7S2A103K050BB)
C36  ValueDisplayed: 0.1uF  [0603L]  (hidden comment: CGA3E2X7R1E104K080AA)
C37  ValueDisplayed: 0.1uF  [0603L]  (hidden comment: CGA3E2X7R1E104K080AA)
C38  PackageReference: 1210  VDC_V: 50V  ValueDisplayed: 10uF  [1210_270]  (hidden comment: UMJ325KB7106KMHT)
C39  PackageReference: 1210  VDC_V: 50V  ValueDisplayed: 10uF  [1210_270]  (hidden comment: UMJ325KB7106KMHT)
C40  PackageReference: 1210  VDC_V: 50V  ValueDisplayed: 10uF  [1210_270]  (hidden comment: UMJ325KB7106KMHT)
C41  PackageReference: 1210  VDC_V: 50V  ValueDisplayed: 10uF  [1210_270]  (hidden comment: UMJ325KB7106KMHT)
C42  PackageReference: 1210  VDC_V: 50V  ValueDisplayed: 10uF  [1210_270]  (hidden comment: UMJ325KB7106KMHT)
C43  Value2: 50V  ValueDisplayed: 0.1uF  [0603]  (hidden comment: CGA3E2X7R1H104K080AA)
C44  Cap_F: 220pF  VDC_V: 100V  [0603_HV]  (hidden comment: 06031C221KAT2A)
C45  Cap_F: 220pF  VDC_V: 100V  [0603_HV]  (hidden comment: 06031C221KAT2A)
C46  Value2: 50V  ValueDisplayed: 0.1uF  [0603]  (hidden comment: CGA3E2X7R1H104K080AA)
C47  PackageReference: 1210  VDC_V: 50V  ValueDisplayed: 10uF  [1210_270]  (hidden comment: UMJ325KB7106KMHT)
C48  PackageReference: 1210  VDC_V: 50V  ValueDisplayed: 10uF  [1210_270]  (hidden comment: UMJ325KB7106KMHT)
C49  PackageReference: 1210  VDC_V: 50V  ValueDisplayed: 10uF  [1210_270]  (hidden comment: UMJ325KB7106KMHT)
C50  PackageReference: 1210  VDC_V: 50V  ValueDisplayed: 10uF  [1210_270]  (hidden comment: UMJ325KB7106KMHT)
C51  PackageReference: 1210  VDC_V: 50V  ValueDisplayed: 10uF  [1210_270]  (hidden comment: UMJ325KB7106KMHT)
C52  Cap_F: 220nF  [0603]  (hidden comment: CGA3E3X7R1H224K080AB)
C53  Cap_F: 220nF  [0603]  (hidden comment: CGA3E3X7R1H224K080AB)
C54  ValueDisplayed: 33pF  [0603L]  (hidden comment: 06031A330JAT2A)
C55  ValueDisplayed: 33pF  [0603L]  (hidden comment: 06031A330JAT2A)
C56  PackageReference: 1210  VDC_V: 50V  ValueDisplayed: 10uF  [1210_270]  (hidden comment: UMJ325KB7106KMHT)
C57  PackageReference: 1210  VDC_V: 50V  ValueDisplayed: 10uF  [1210_270]  (hidden comment: UMJ325KB7106KMHT)
C58  PackageReference: 1210  VDC_V: 50V  ValueDisplayed: 10uF  [1210_270]  (hidden comment: UMJ325KB7106KMHT)
C59  PackageReference: 1210  VDC_V: 50V  ValueDisplayed: 10uF  [1210_270]  (hidden comment: UMJ325KB7106KMHT)
C60  PackageReference: 1210  VDC_V: 50V  ValueDisplayed: 10uF  [1210_270]  (hidden comment: UMJ325KB7106KMHT)
C61  PackageReference: 1210  VDC_V: 50V  ValueDisplayed: 10uF  [1210_270]  (hidden comment: UMJ325KB7106KMHT)
C62  PackageReference: 1210  VDC_V: 50V  ValueDisplayed: 10uF  [1210_270]  (hidden comment: UMJ325KB7106KMHT)
C63  PackageReference: 1210  VDC_V: 50V  ValueDisplayed: 10uF  [1210_270]  (hidden comment: UMJ325KB7106KMHT)
C64  PackageReference: 1210  VDC_V: 50V  ValueDisplayed: 10uF  [1210_270]  (hidden comment: UMJ325KB7106KMHT)
C65  PackageReference: 1210  VDC_V: 50V  ValueDisplayed: 10uF  [1210_270]  (hidden comment: UMJ325KB7106KMHT)
C66  Cap_F: 1µF  VDC_V: 25V  [0603S]  (hidden comment: CGA3E1X7R1E105K080AC)
C67  ValueDisplayed: 0.22µF  [0603L]  (hidden comment: CL10B224KO8VPNC)
C68  ValueDisplayed: 0.22µF  [0603L]  (hidden comment: CL10B224KO8VPNC)
C69  VDC_V: 50V  ValueDisplayed: 100pF  [0603]  (hidden comment: CGA3E2NP01H101J080AA)
C70  VDC_V: 50V  ValueDisplayed: 3300pF  [0603]  (hidden comment: GRM1885C1H332JA01D)
D9  BAT46WJ,115  [SOD-323F]
D10  BAT46WJ,115  [SOD-323F]
D11  BAT46WJ,115  [SOD-323F]
J2  1040  [CONN_1040]  (value not drawn)
J3  EM292902-UL  [Eaton_EM292902]  (value not drawn)
J4  TSW-114-07-G-S  [TSW-114-07-G-S]  (value not drawn)
L2  XGL1010-682MED  value 6.8uH  DCR_ohm: 7.0m  [FP-XGL1010-103MED_SMT_IND_10MM0_11MM3-MFG]
L3  XGL1010-682MED  value 6.8uH  DCR_ohm: 7.0m  [FP-XGL1010-103MED_SMT_IND_10MM0_11MM3-MFG]
NT1  Net-Tie  [Net-Tie_10mil]  (net tie, no BOM)
Q5  NVMFS5C670NLWFAFT1G  [SO-8FL]
Q6  NVMFS5C670NLWFAFT1G  [SO-8FL]
Q7  NVMFS5C670NLWFAFT1G  [SO-8FL]
Q8  NVMFS5C670NLWFAFT1G  [SO-8FL]
R22  ValueDisplayed: 1.00  [0603L]  (hidden comment: RC0603FR-071RL)
R23  ValueDisplayed: 0  [0402L]  (hidden comment: ERJ-2GE0R00X)
R24  ValueDisplayed: 0  [0402L]  (hidden comment: ERJ-2GE0R00X)
R25  ValueDisplayed: 100k  [0603L]  (hidden comment: CRCW0603100KFKEA)
R26  ValueDisplayed: 0  [0402L]  (hidden comment: ERJ-2GE0R00X)
R27  ValueDisplayed: 0  [0402L]  (hidden comment: ERJ-2GE0R00X)
R28  ValueDisplayed: 100k  [0603L]  (hidden comment: CRCW0603100KFKEA)
R29  ValueDisplayed: 10.5k  [0603]  (hidden comment: CRCW060310K5FKEA)
R30  ValueDisplayed: 10.5k  [0603]  (hidden comment: CRCW060310K5FKEA)
R31  ValueDisplayed: 2.2  [0805_HV]  (hidden comment: ERJ-6GEYJ2R2V)
R32  ValueDisplayed: 2.2  [0805_HV]  (hidden comment: ERJ-6GEYJ2R2V)
R33  ValueDisplayed: 10.0k  [0603]  (hidden comment: RMCF0603FT10K0)
R34  ValueDisplayed: 10.0k  [0603]  (hidden comment: RMCF0603FT10K0)
R35  ValueDisplayed: 100k  [0603L]  (hidden comment: CRCW0603100KFKEA)
R36  ValueDisplayed: 100k  [0603L]  (hidden comment: CRCW0603100KFKEA)
R37  ValueDisplayed: 0  [0603L]  (hidden comment: CRCW06030000Z0EA)
R38  ValueDisplayed: 100  [0603L]  (hidden comment: CRCW0603100RFKEA)
R39  ValueDisplayed: 100  [0603L]  (hidden comment: CRCW0603100RFKEA)
R40  ValueDisplayed: 0  [0603L]  (hidden comment: CRCW06030000Z0EA)
R41  ValueDisplayed: 487k  [0603]  (hidden comment: CRCW0603487KFKEA)
R42  ValueDisplayed: 1.65k  [0603]  (hidden comment: RT0603DRE071K65L)
R43  ValueDisplayed: 49.9k  [0603]  (hidden comment: CRCW060349K9FKEA)
R44  ValueDisplayed: 100k  [0603L]  (hidden comment: CRCW0603100KFKEA)
R45  ValueDisplayed: 100k  [0603L]  (hidden comment: CRCW0603100KFKEA)
R46  ValueDisplayed: 100k  [0603L]  (hidden comment: CRCW0603100KFKEA)
R47  ValueDisplayed: 100k  [0603L]  (hidden comment: CRCW0603100KFKEA)
R48  ValueDisplayed: 54.9k  [0603L]  (hidden comment: CRCW060354K9FKEA)
R49  ValueDisplayed: 11.5k  [0603]  (hidden comment: CRCW060311K5FKEA)
R50  ValueDisplayed: 10.0k  [TNPW0603]  (hidden comment: TNPW060310K0BEEA)
R51  ValueDisplayed: 0  [0603L]  (hidden comment: CRCW06030000Z0EA)
SH-J1  M7582-05  [Harwin_M7582-05]
TP3  5015  [Testpoint_Keystone_Miniature]
TP4  5015  [Testpoint_Keystone_Miniature]  (value not drawn)
TP5  5015  [Testpoint_Keystone_Miniature]  (value not drawn)
U2  LM5143QRHARQ1  [RHA0040N-MFG]

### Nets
AGND: C18.1 C66.1 C67.2 C68.2 C69.2 C70.2 J4.8 NT1.1 R48.1 R50.1 R51.2 U2.3(FB2) U2.35(AGND)
PGND: C17.1 C19.2 C20.2 C21.2 C22.2 C23.2 C24.2 C25.2 C26.2 C27.2 C28.2 C29.2 C30.2 C31.2 C32.2 C33.2 C34.2 C35.2 C38.2 C39.2 C40.2 C41.2 C42.2 C43.2 C46.2 C47.2 C48.2 C49.2 C50.2 C51.2 C56.2 C57.2 C58.2 C59.2 C60.2 C61.2 C62.2 C63.2 C64.2 C65.2 J2.1 J3.2 J4.1 J4.14 NT1.2 Q7.1(S) Q7.2(S) Q7.3(S) Q8.1(S) Q8.2(S) Q8.3(S) R31.1 R32.1 R35.2 R36.1 TP5.1 U2.14(PGND2) U2.17(PGND1) U2.41(EP)
VCC: C24.1 C25.1 D9.2(A) D10.2(A) J4.3 R44.2 R45.2 U2.15(VCC) U2.16(VCC)
VDDA: C18.2 J4.6 U2.34(MODE) U2.36(VDDA)
VIN: C17.2 C20.1 C21.1 C22.1 C23.1 C26.1 C27.1 C28.1 C29.1 C30.1 C31.1 C32.1 C33.1 C34.1 C35.1 J4.12 Q5.5(D) Q6.5(D) R46.2 R47.2 U2.25(VIN)
VOUT: C38.1 C39.1 C40.1 C41.1 C42.1 C43.1 C46.1 C47.1 C48.1 C49.1 C50.1 C51.1 C52.2 C53.1 C56.1 C57.1 C58.1 C59.1 C60.1 C61.1 C62.1 C63.1 C64.1 C65.1 J3.1 L2.2 L3.2 R33.1 R34.2 R37.2 R40.2 R41.2 TP4.1
A: J4.13 ; off-sheet A
COMP: C69.1 D11.2(A) R49.2 U2.2(COMP2) U2.29(COMP1) ; off-sheet COMP
DEMB: J4.7 U2.33(DEMB) ; off-sheet DEMB
EN1: J4.10 R47.1 U2.31(EN1) ; off-sheet EN1
EN2: J4.2 R46.1 U2.40(EN2) ; off-sheet EN2
FB1: R41.1 R43.2 R50.2 U2.28(FB1) ; off-sheet FB1
PG1: J4.9 R45.1 U2.24(PG1) ; off-sheet PG1
PG2: J4.4 R44.1 U2.7(PG2) ; off-sheet PG2
SS: C67.1 D11.1(K) U2.1(SS2) U2.30(SS1) ; off-sheet SS
SYNCOUT: J4.5 U2.39(SYNCOUT) ; off-sheet SYNCOUT
VPWM: J4.11 R42.1 ; off-sheet VPWM
NetC19_1: C19.1 R22.1 U2.6(VCCX)
NetC36_1: C36.1 C44.1 L2.1 Q5.1(S) Q5.2(S) Q5.3(S) Q7.5(D) R25.2 R29.2 U2.21(SW1)
NetC36_2: C36.2 D9.1(K) U2.20(HB1)
NetC37_1: C37.1 C45.1 L3.1 Q6.1(S) Q6.2(S) Q6.3(S) Q8.5(D) R28.1 R30.1 U2.10(SW2)
NetC37_2: C37.2 D10.1(K) U2.11(HB2)
NetC44_2: C44.2 R31.2
NetC45_2: C45.2 R32.2
NetC52_1: C52.1 R29.1 R33.2 R38.2
NetC53_2: C53.2 R30.2 R34.1 R39.2
NetC54_1: C54.1 R37.1 U2.26(VOUT1)
NetC54_2: C54.2 R38.1 U2.27(CS1)
NetC55_1: C55.1 R40.1 U2.5(VOUT2)
NetC55_2: C55.2 R39.1 U2.4(CS2)
NetC66_2: C66.2 R42.2 R43.1
NetC68_1: C68.1 U2.32(RES)
NetC70_1: C70.1 R49.1
NetQ5_4: Q5.4(G) R23.1 R25.1 R26.1
NetQ6_4: Q6.4(G) R24.2 R27.2 R28.2
NetQ7_4: Q7.4(G) R35.1 U2.18(LO1) U2.19(LOL1)
NetQ8_4: Q8.4(G) R36.2 U2.12(LOL2) U2.13(LO2)
NetR22_2: R22.2 TP3.1
NetR23_2: R23.2 U2.22(HO1)
NetR24_1: R24.1 U2.9(HO2)
NetR26_2: R26.2 U2.23(HOL1)
NetR27_1: R27.1 U2.8(HOL2)
NetR48_2: R48.2 U2.37(RT)
NetR51_1: R51.1 U2.38(DITH)

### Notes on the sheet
- For a 2 ohm load:
  12V * 6A = 72W
  24V * 12A = 280W
  40V * 20A = 800W
- 6-35VDC
- (near TP4) 300W Continuous
- OUTPUT:
- 1000W Peak 100ms
- Use 3.3V 100kHz PWM signal:
  VPWM=0% for VOUT=35.1V
  VPWM=50% for VOUT=20.5V
  VPWM=100% for VOUT=5.9V
- (near R48) for 400kHz operation
- for two phase
- (near R51) Test with dithering off
- (near SH-J1) use SH-J1 to jumper J4-6 to J4-7
- DEMB jumper settings:
  VDDA for FPWM
  AGND for DEM
  OPEN for external clock, FPWM

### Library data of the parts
C17 = CMP-0008374-2: CAP, CERM, 0.47 uF, 100 V, +/- 10%, X7R, 0805; Manufacturer: MuRata; TaMin_C: -55°C; Polarized: N; SizeAreaWB_mm2: 6.75; Value1: Unknown; U/M: EA; Value: 0.47uF; TaMax_C: 125°C; SizeZ_mm: 1.45; SizeX_mm: 2; SizeY_mm: 1.25; Cap_Case: 0805; SizeArea_mm2: 2.5; CompType: Capacitor; Cap_F: 470nF; AEC Category: Q200
C18 = CMP-0007138-4: CAP, CERM, 0.47 uF, 16 V, +/- 10%, X7R, AEC-Q200 Grade 1, 0603; Manufacturer: MuRata; TaMin_C: -55°C; Polarized: N; SizeAreaWB_mm2: 4.68; Value1: Unknown; U/M: EA; Value: 0.47uF; TaMax_C: 125°C; SizeZ_mm: 1; SizeX_mm: 1.6; SizeY_mm: 0.8; Cap_Case: 0603; Value2: 16V; SizeArea_mm2: 1.28; CompType: Capacitor; AEC Qualified: Y; Cap_F: 470nF; AEC Category: Q200
C19 = CMP-0007370-4: CAP, CERM, 2.2 uF, 10 V, +/- 10%, X7R, 0603; Manufacturer: MuRata; TaMin_C: -55°C; Polarized: N; SizeAreaWB_mm2: 4.68; Value1: 0.009 ohm; U/M: EA; Value: 2.2uF; TaMax_C: 125°C; SizeZ_mm: 1; SizeX_mm: 1.6; SizeY_mm: 0.8; Cap_Case: 0603; Value2: 10V; SizeArea_mm2: 1.28; CompType: Capacitor; Cap_F: 2.2µF; AEC Category: Q200; ESR_ohm: 9m
C20-C23 C26-C29 = CMP-0082268-1: as C5 on sheet PMP23468-SH1
C24 C25 = CMP-0007370-4: CAP, CERM, 2.2 uF, 10 V, +/- 10%, X7R, 0603; Manufacturer: MuRata; TaMin_C: -55°C; ESR_ohm: 9m; Polarized: N; SizeAreaWB_mm2: 4.68; Value1: 0.009 ohm; U/M: EA; Value: 2.2uF; TaMax_C: 125°C; SizeZ_mm: 1; SizeX_mm: 1.6; SizeY_mm: 0.8; Cap_Case: 0603; Value2: 10V; SizeArea_mm2: 1.28; CompType: Capacitor; Cap_F: 2.2µF; AEC Category: Q200
C30-C35 = CMP-0006333-2: CAP, CERM, 0.01 uF, 100 V, +/- 10%, X7S, AEC-Q200 Grade 1, 0402; Manufacturer: TDK; TaMin_C: -55°C; ESR_ohm: 0.4102; Polarized: N; SizeAreaWB_mm2: 3; Value1: 0.410191 ohm; U/M: EA; Value: 0.01uF; TaMax_C: 125°C; SizeZ_mm: 0.6; SizeX_mm: 1; SizeY_mm: 0.5; Cap_Case: 0402; AEC Qualified: Y; Cap_F: 10nF; IRMS_A: 291.729mA; AEC Category: Q200
C36 C37 = CMP-0007077-5: CAP, CERM, 0.1 uF, 25 V, +/- 10%, X7R, AEC-Q200 Grade 1, 0603; Manufacturer: TDK; TaMin_C: -55°C; Polarized: N; SizeAreaWB_mm2: 4.68; Value1: Unknown; U/M: EA; Value: 0.1uF; TaMax_C: 125°C; SizeZ_mm: 1; SizeX_mm: 1.6; SizeY_mm: 0.8; Cap_Case: 0603; Value2: 25V; SizeArea_mm2: 1.28; AEC Qualified: Y; Cap_F: 100nF; AEC Category: Q200
C38-C42 C47-C51 C56-C65 = CMP-0009257-2: CAP, CERM, 10 uF, 50 V, +/- 10%, X7R, AEC-Q200 Grade 1, 1210; Manufacturer: Taiyo Yuden; TaMin_C: -55°C; Polarized: N; SizeAreaWB_mm2: 14.7; Value1: Unknown; Value: 10uF; TaMax_C: 125°C; SizeZ_mm: 2.7; SizeX_mm: 3.2; SizeY_mm: 2.5; SizeArea_mm2: 8; AEC Qualified: Y; Cap_F: 10µF; AEC Grade: 1; AEC Category: Q200; U/M: EA
C43 C46 = CMP-0007078-4: CAP, CERM, 0.1 uF, 50 V, +/- 10%, X7R, AEC-Q200 Grade 1, 0603; Manufacturer: TDK; TaMin_C: -55°C; Polarized: N; SizeAreaWB_mm2: 4.68; Value1: 0.0296 ohm; U/M: EA; Value: 0.1uF; TaMax_C: 125°C; SizeZ_mm: 1; SizeX_mm: 1.6; SizeY_mm: 0.8; SizeArea_mm2: 1.28; AEC Qualified: Y; Cap_F: 100nF; AEC Category: Q200; ESR_ohm: 29.6m; IRMS_A: 971.99mA
C44 C45 = CMP-0006735-5: CAP, CERM, 220 pF, 100 V, +/- 10%, X7R, 0603; Manufacturer: AVX; TaMin_C: -55°C; ESR_ohm: 0.579; Polarized: N; SizeAreaWB_mm2: 4.68; Value1: 0.579 ohm; U/M: EA; Value: 220pF; TaMax_C: 125°C; SizeZ_mm: 1; SizeX_mm: 1.6; SizeY_mm: 0.8; Cap_Case: 0603; SizeArea_mm2: 1.28; AEC Category: Q200
C52 C53 = CMP-0007094-5: CAP, CERM, 0.22 uF, 50 V, +/- 10%, X7R, AEC-Q200 Grade 1, 0603; Manufacturer: TDK; TaMin_C: -55°C; ESR_ohm: 21.699m; Polarized: N; SizeAreaWB_mm2: 4.68; Value1: 0.021699 ohm; U/M: EA; Value: 0.22uF; TaMax_C: 125°C; SizeZ_mm: 1; SizeX_mm: 1.6; SizeY_mm: 0.8; Value2: 50V; SizeArea_mm2: 1.28; AEC Qualified: Y; IRMS_A: 1.125A; AEC Category: Q200
C54 C55 = CMP-0006722-4: CAP, CERM, 33 pF, 100 V, +/- 5%, C0G/NP0, 0603; Manufacturer: AVX; TaMin_C: -55°C; ESR_ohm: 2.09d; Polarized: N; SizeAreaWB_mm2: 4.68; Value1: 0.209 ohm; U/M: EA; Value: 33pF; TaMax_C: 125°C; SizeZ_mm: 1; SizeX_mm: 1.6; SizeY_mm: 0.8; Cap_Case: 0603; Value2: 100V; SizeArea_mm2: 1.28; CompType: Capacitor; AEC Category: Q200
C66 = CMP-0076705-3: CAP, CERM, 1 µF, 25 V,+/- 10%, X7R, AEC-Q200 Grade 1, 0603; Manufacturer: TDK; SizeAreaWB_mm2: 4.68; SizeArea_mm2: 1.28; AEC Qualified: Y; AEC Category: Q200; Value: 1uF; TaMax_C: 125°C; SizeZ_mm: 1.0; AEC Grade: 1; Polarized: N; TaMin_C: -55°C; SizeY_mm: 0.8; U/M: EA; SizeX_mm: 1.6; Cap_Case: 1.6x0.8x0.8mm
C67 C68 = CMP-0080102-1: CAP, CERM, 0.22 µF, 16 V,+/- 10%, X7R, AEC-Q200 Grade 1, 0603; Manufacturer: Samsung; TaMin_C: -55°C; Polarized: N; SizeAreaWB_mm2: 4.68; U/M: EA; Value: 0.22uF; TaMax_C: 125°C; SizeZ_mm: 1; SizeX_mm: 1.6; SizeY_mm: 0.8; Cap_Case: 0603; Value2: 16V; SizeArea_mm2: 1.28; CompType: Capacitor; AEC Qualified: Y; Cap_F: 220nF; AEC Category: Q200
C69 = CMP-0007075-4: CAP, CERM, 100 pF, 50 V, +/- 5%, C0G/NP0, AEC-Q200 Grade 0, 0603; Manufacturer: TDK; TaMin_C: -55°C; Polarized: N; SizeAreaWB_mm2: 4.68; Value1: Unknown; U/M: EA; Value: 100pF; TaMax_C: 150°C; SizeZ_mm: 1; SizeX_mm: 1.6; SizeY_mm: 0.8; SizeArea_mm2: 1.28; AEC Qualified: Y; AEC Grade: 0; AEC Category: Q200
C70 = CMP-0007210-4: CAP, CERM, 3300 pF, 50 V, +/- 5%, C0G/NP0, 0603; Manufacturer: MuRata; TaMin_C: -55°C; Polarized: N; SizeAreaWB_mm2: 4.68; Value1: Unknown; U/M: EA; Value: 3300pF; TaMax_C: 125°C; SizeZ_mm: 1; SizeX_mm: 1.6; SizeY_mm: 0.8; SizeArea_mm2: 1.28; Cap_F: 3.3nF; AEC Category: Q200
D9-D11 = CMP-0076946-2: Diode, Schottky, 100 V, 0.25 A, SOD-323F; Manufacturer: Nexperia; SizeAreaWB_mm2: 7.875; Value2: 0.85V; SizeX_mm: 2.5; Green_REACh: Incomplete; SizeArea_mm2: 3.125; Vf_V: 850mV; Green_Lifecycle: Not Set; Vr_V: 100V; TJmax_C: 150°C; Value1: 0.25A; Io_A: 250mA; SizeZ_mm: 0.8; Value: 100V; AEC Category: Q101; SizeY_mm: 1.25
J2 = CMP-0055161-1: TEST POINT SLOTTED .118", TH; Manufacturer: Keystone; CNHeader: FALSE; Green_Lifecycle: Active; Green_REACh: Passed; CT: TRUE
J3 = CMP-0077513-2: Terminal Block, 10.16mm, 2x1, Tin, R/A, TH; Manufacturer: Eaton; Pitch_mm: 10.16; Gender: Female; Voltage_V: 300V; Current_A: 65A; Cert_CULUS: Y; Row_Count: 1
J4 = CMP-0075428-1: Header, 100mil, 14x1, Gold, TH; Manufacturer: Samtec; Pitch_mm: 2.54; Cert_VDE: N; Gender: Male; Cert_CSA: Y; Current_A: 6.3A; Voltage_V: 550V; CT: False; Row_Count: 1; CNHeader: True; Green_Lifecycle: Active; Green_REACh: Passed
L2 L3 = CMP-0120510-1: 6.8 µH Shielded Molded Inductor 21.2 A 7.0mOhm Max Nonstandard; Manufacturer: Coilcraft; PartNumber: XGL1010-103MED; AEC Grade: Grade 1; AEC Qualified: Yes; Ind_H: 10µH; Irms: 18.2A; Isat: 8.3A; Material: Composite; SizeZ_mm: 10mm; Self Resonant Frequency: 12MHz; Shrouded: true; TaMax_C: +125°C; TaMin_C: -40°C; Test Frequency: 1MHz; Tolerance_%: 20%
NT1 = CMP-0078142-6: Single point connection between nets.
Q5 Q6 = CMP-0750168-1: MOSFET, N-CH, 60 V, 17 A, AEC-Q101, SO-8FL; Manufacturer: ON Semiconductor; Alternate Manufacturer: None; IdsMax_A: 17A; VdsMax_V: 60V; QgTyp_nC: 20; AEC Qualified: Y; Rdson45_ohm: 8.8m; Vgs_V: 20V; SizeZ_mm: 1.1; ChMode: Enhancement; SizeAreaWB_mm2: 58.2725; Value1: 0.0088 ohm; ChType: N; SizeArea_mm2: 31.6725; SizeX_mm: 6.15; SizeY_mm: 5.15; Value2: 20 nC; AEC Category: Q101; Value: 60V
Q7 Q8 = CMP-0750168-1: MOSFET, N-CH, 60 V, 17 A, AEC-Q101, SO-8FL; Manufacturer: ON Semiconductor; Alternate Manufacturer: None; AEC Qualified: Y; IdsMax_A: 17A; QgTyp_nC: 20; Rdson45_ohm: 8.8m; SizeZ_mm: 1.1; VdsMax_V: 60V; Vgs_V: 20V; ChMode: Enhancement; SizeAreaWB_mm2: 58.2725; Value1: 0.0088 ohm; ChType: N; SizeArea_mm2: 31.6725; SizeX_mm: 6.15; SizeY_mm: 5.15; Value2: 20 nC; AEC Category: Q101; Value: 60V
R22 = CMP-0022900-4: RES, 1.00, 1%, 0.1 W, 0603; Manufacturer: Yageo; Power_W: 100mW; TempCo: 200 ppm/C; Value_Code: 1R00; Value: 1.00; EIA_Code: E96; Res_ohm: 1; SizeX_mm: 1.6; SizeY_mm: 0.8; Value2: 0.1W; SizeArea_mm2: 1.28; CompType: Resistor; AEC Qualified: N; VDC_V: 75V; AEC Category: Q200; SizeAreaWB_mm2: 4.68
R23 R24 R26 R27 = CMP-0026992-3: RES, 0, 5%, 0.1 W, AEC-Q200 Grade 0, 0402; Manufacturer: Panasonic; Power_W: 100mW; TempCo: 600 ppm/C; Value_Code: 0000; Value: 0; EIA_Code: E24; SizeX_mm: 1; SizeY_mm: 0.5; SizeZ_mm: 0.6; Value2: 0.1W; AEC Qualified: Y; VDC_V: 50V; AEC Category: Q200; SizeAreaWB_mm2: 3
R25 R28 R35 R36 R44-R47 = CMP-0021990-4: RES, 100 k, 1%, 0.1 W, AEC-Q200 Grade 0, 0603; Manufacturer: Vishay-Dale; Power_W: 100mW; TempCo: 100 ppm/C; Value: 100k; EIA_Code: E96; SizeX_mm: 1.6; SizeY_mm: 0.8; SizeZ_mm: 1; Value2: 0.1W; SizeArea_mm2: 1.28; CompType: Resistor; AEC Qualified: Y; VDC_V: 75V; AEC Category: Q200; AEC Grade: 0
R29 R30 = CMP-0022000-4: RES, 10.5 k, 1%, 0.1 W, AEC-Q200 Grade 0, 0603; Manufacturer: Vishay-Dale; Power_W: 100mW; TempCo: 100 ppm/C; Value_Code: 10k5; Value: 10.5k; EIA_Code: E96; SizeX_mm: 1.6; SizeY_mm: 0.8; SizeZ_mm: 1; Value2: 0.1W; SizeArea_mm2: 1.28; AEC Qualified: Y; VDC_V: 75V; AEC Category: Q200; AEC Grade: 0
R31 R32 = CMP-0020693-3: RES, 2.2, 5%, 0.125 W, AEC-Q200 Grade 0, 0805; Manufacturer: Panasonic; Power_W: 125mW; TempCo: 600 ppm/C; Value_Code: 2R20; Value: 2.2; EIA_Code: E24; SizeX_mm: 2; SizeY_mm: 1.25; SizeZ_mm: 1.45; Value2: 0.125W; SizeArea_mm2: 2.5; AEC Qualified: Y; VDC_V: 150V; AEC Category: Q200; AEC Grade: 0; SizeAreaWB_mm2: 6.75
R33 R34 = CMP-0023341-3: as R15 on sheet PMP23468-SH1
R37 R40 = CMP-0025697-4: RES, 0, 5%, 0.1 W, AEC-Q200 Grade 0, 0603; Manufacturer: Vishay-Dale; Power_W: 100mW; TempCo: 200 ppm/C; Value_Code: 0000; Value: 0; EIA_Code: E24; SizeX_mm: 1.6; SizeY_mm: 0.8; SizeZ_mm: 1; Value2: 0.1W; SizeArea_mm2: 1.28; CompType: Resistor; AEC Qualified: Y; VDC_V: 75V; AEC Category: Q200
R38 R39 = CMP-0021991-4: RES, 100, 1%, 0.1 W, AEC-Q200 Grade 0, 0603; Manufacturer: Vishay-Dale; Power_W: 100mW; TempCo: 100 ppm/C; Value_Code: 100R; Value: 100; EIA_Code: E96; SizeX_mm: 1.6; SizeY_mm: 0.8; SizeZ_mm: 1; Value2: 0.1W; SizeArea_mm2: 1.28; AEC Qualified: Y; VDC_V: 75V; AEC Category: Q200; AEC Grade: 0
R41 = CMP-0022441-4: RES, 487 k, 1%, 0.1 W, AEC-Q200 Grade 0, 0603; Manufacturer: Vishay-Dale; Power_W: 100mW; TempCo: 100 ppm/C; Value: 487k; EIA_Code: E96; SizeX_mm: 1.6; SizeY_mm: 0.8; SizeZ_mm: 1; Value2: 0.1W; SizeArea_mm2: 1.28; AEC Qualified: Y; VDC_V: 75V; AEC Category: Q200; AEC Grade: 0
R42 = CMP-0024835-1: RES, 1.65 k, 0.5%, 0.1 W, 0603; Manufacturer: Yageo America; Power_W: 100mW; TempCo: 50 ppm/C; Value_Code: 1k65; U/M: EA; Value: 1.65k; EIA_Code: E192; SizeX_mm: 1.6; SizeY_mm: 0.8; SizeZ_mm: 1; Value2: 0.1W; SizeArea_mm2: 1.28; VDC_V: 75V; AEC Category: Q200
R43 = CMP-0022447-2: RES, 49.9 k, 1%, 0.1 W, 0603; Manufacturer: Vishay-Dale; Power_W: 100mW; TempCo: 100 ppm/C; Value_Code: 49k9; U/M: EA; Value: 49.9k; EIA_Code: E96; SizeX_mm: 1.6; SizeY_mm: 0.8; SizeZ_mm: 1; Value2: 0.1W; SizeArea_mm2: 1.28; VDC_V: 75V; AEC Category: Q200
R48 = CMP-0022494-4: RES, 54.9 k, 1%, 0.1 W, AEC-Q200 Grade 0, 0603; Manufacturer: Vishay-Dale; Power_W: 100mW; TempCo: 100 ppm/C; Value_Code: 54k9; Value: 54.9k; EIA_Code: E96; SizeX_mm: 1.6; SizeY_mm: 0.8; SizeZ_mm: 1; Value2: 0.1W; SizeArea_mm2: 1.28; AEC Qualified: Y; VDC_V: 75V; AEC Category: Q200; AEC Grade: 0
R49 = CMP-0022018-4: RES, 11.5 k, 1%, 0.1 W, AEC-Q200 Grade 0, 0603; Manufacturer: Vishay-Dale; Power_W: 100mW; TempCo: 100 ppm/C; Value_Code: 11k5; Value: 11.5k; EIA_Code: E96; SizeX_mm: 1.6; SizeY_mm: 0.8; SizeZ_mm: 1; Value2: 0.1W; SizeArea_mm2: 1.28; AEC Qualified: Y; VDC_V: 75V; AEC Category: Q200; AEC Grade: 0
R50 = CMP-0025686-1: RES, 10.0 k, 0.1%, 0.1 W, AEC-Q200 Grade 1, 0603; Manufacturer: Vishay-Dale; Power_W: 100mW; TempCo: 25 ppm/C; Value_Code: 10k0; U/M: EA; Value: 10.0k; EIA_Code: E192; Res_ohm: 10k; SizeX_mm: 1.6; SizeY_mm: 0.85; SizeZ_mm: 0.55; Value2: 0.1W; SizeArea_mm2: 1.36; AEC Qualified: Y; VDC_V: 75V; AEC Grade: 1; AEC Category: Q200
R51 = CMP-0025697-4: RES, 0, 5%, 0.1 W, AEC-Q200 Grade 0, 0603; Manufacturer: Vishay-Dale; Power_W: 100mW; TempCo: 200 ppm/C; Value_Code: 0000; Value: 0; EIA_Code: E24; SizeX_mm: 1.6; SizeY_mm: 0.8; SizeZ_mm: 1; Value2: 0.1W; SizeArea_mm2: 1.28; AEC Qualified: Y; VDC_V: 75V; AEC Category: Q200
SH-J1 = CMP-0078738-1: Single Operation 2.54mm Pitch Open Top Jumper Socket; Manufacturer: Harwin; CompType: Shunt
TP3-TP5 = CMP-0055152-2: as TP1 on sheet PMP23468-SH1
U2 = CMP-0094639-1: Automotive 3.5-V to 65-V Dual Synchronous Buck Controller With Low IQ; Manufacturer: Texas Instruments; TaMin_C: -40°C; SizeZ_mm: 1mm; Switching Frequency: 0.1-2.2MHz; Standoff Height: 0mm; Number Of Outputs: 2; AEC Grade: Grade 1; Output Type: Fixed,AdjustableProgrammable; TJmax_C: +150°C; Min Supply Voltage: 3.5V; AEC Qualified: Yes; Nominal Supply Current: 15-25uA; TaMax_C: +125°C; Output Voltage: 0.6-55V; Max Supply Voltage: 65V

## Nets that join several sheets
PGND: PMP23468-SH1 (25 pins), PMP23468-SH2 (59 pins)
VIN: PMP23468-SH1 (5 pins), PMP23468-SH2 (21 pins)
A: PMP23468-SH1 (8 pins), PMP23468-SH2 (J4.13)

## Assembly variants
001: not fitted FID1 FID2 FID3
